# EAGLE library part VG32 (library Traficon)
PCB EUROCARD, 32-pin type C/AC, 5.08 mm
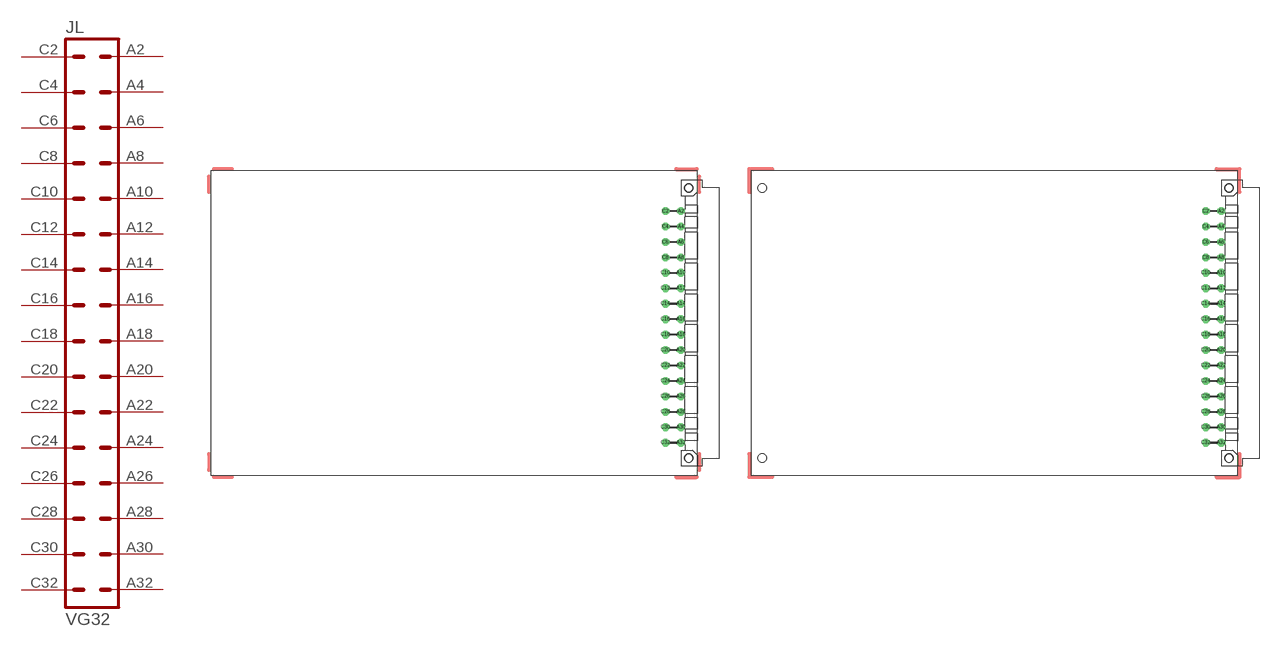
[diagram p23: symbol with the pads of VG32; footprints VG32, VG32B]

Designator prefix JL

## VG32  [VG32]
A2  A2  pas
A4  A4  pas
A6  A6  pas
A8  A8  pas
A10  A10  pas
A12  A12  pas
A14  A14  pas
A16  A16  pas
A18  A18  pas
A20  A20  pas
A22  A22  pas
A24  A24  pas
A26  A26  pas
A28  A28  pas
A30  A30  pas
A32  A32  pas
C2  C2  pas
C4  C4  pas
C6  C6  pas
C8  C8  pas
C10  C10  pas
C12  C12  pas
C14  C14  pas
C16  C16  pas
C18  C18  pas
C20  C20  pas
C22  C22  pas
C24  C24  pas
C26  C26  pas
C28  C28  pas
C30  C30  pas
C32  C32  pas

## VG32B  [VG32B]
Pads as for VG32

## VG32K  [VG32K]
Pads as for VG32

## VG32KB  [VG32KB]
Pads as for VG32

## VG32P  [VG32P]
Pads as for VG32

## Footprint VG32 (pad centres in mm)
EUROCARD, C/AC, 5.08
drill 1.016 pad 2.54 octagon: A2 154.94,36.83; A4 154.94,31.75; A6 154.94,26.67; A8 154.94,21.59; A10 154.94,16.51; A12 154.94,11.43; A14 154.94,6.35; A16 154.94,1.27; A18 154.94,-3.81; A20 154.94,-8.89; A22 154.94,-13.97; A24 154.94,-19.05; A26 154.94,-24.13; A28 154.94,-29.21; A30 154.94,-34.29; A32 154.94,-39.37; C2 149.86,36.83; C4 149.86,31.75; C6 149.86,26.67; C8 149.86,21.59; C10 149.86,16.51; C12 149.86,11.43; C14 149.86,6.35; C16 149.86,1.27; C18 149.86,-3.81; C20 149.86,-8.89; C22 149.86,-13.97; C24 149.86,-19.05; C26 149.86,-24.13; C28 149.86,-29.21; C30 149.86,-34.29; C32 149.86,-39.37
hole 2.794 at 157.48,44.45
hole 2.794 at 157.48,-44.45

## Footprint VG32B (pad centres in mm)
EUROCARD, 4 mounting holes, C/AC, 5.08
drill 1.016 pad 2.54 octagon: A2 154.94,36.83; A4 154.94,31.75; A6 154.94,26.67; A8 154.94,21.59; A10 154.94,16.51; A12 154.94,11.43; A14 154.94,6.35; A16 154.94,1.27; A18 154.94,-3.81; A20 154.94,-8.89; A22 154.94,-13.97; A24 154.94,-19.05; A26 154.94,-24.13; A28 154.94,-29.21; A30 154.94,-34.29; A32 154.94,-39.37; C2 149.86,36.83; C4 149.86,31.75; C6 149.86,26.67; C8 149.86,21.59; C10 149.86,16.51; C12 149.86,11.43; C14 149.86,6.35; C16 149.86,1.27; C18 149.86,-3.81; C20 149.86,-8.89; C22 149.86,-13.97; C24 149.86,-19.05; C26 149.86,-24.13; C28 149.86,-29.21; C30 149.86,-34.29; C32 149.86,-39.37
hole 2.794 at 157.48,44.45
hole 2.794 at 157.48,-44.45
hole 2.794 at 3.81,-44.45
hole 2.794 at 3.81,44.45

## Footprint VG32K (pad centres in mm)
EUROCARD, 2 mounting holes, C/AC, 5.08
drill 1.016 pad 2.54 octagon: A2 154.94,36.83; A4 154.94,31.75; A6 154.94,26.67; A8 154.94,21.59; A10 154.94,16.51; A12 154.94,11.43; A14 154.94,6.35; A16 154.94,1.27; A18 154.94,-3.81; A20 154.94,-8.89; A22 154.94,-13.97; A24 154.94,-19.05; A26 154.94,-24.13; A28 154.94,-29.21; A30 154.94,-34.29; A32 154.94,-39.37; C2 149.86,36.83; C4 149.86,31.75; C6 149.86,26.67; C8 149.86,21.59; C10 149.86,16.51; C12 149.86,11.43; C14 149.86,6.35; C16 149.86,1.27; C18 149.86,-3.81; C20 149.86,-8.89; C22 149.86,-13.97; C24 149.86,-19.05; C26 149.86,-24.13; C28 149.86,-29.21; C30 149.86,-34.29; C32 149.86,-39.37
hole 2.794 at 157.48,44.45
hole 2.794 at 157.48,-44.45

## Footprint VG32KB (pad centres in mm)
EUROCARD, 4 mounting holes, C/AC, 5.08
drill 1.016 pad 2.54 octagon: A2 154.94,36.83; A4 154.94,31.75; A6 154.94,26.67; A8 154.94,21.59; A10 154.94,16.51; A12 154.94,11.43; A14 154.94,6.35; A16 154.94,1.27; A18 154.94,-3.81; A20 154.94,-8.89; A22 154.94,-13.97; A24 154.94,-19.05; A26 154.94,-24.13; A28 154.94,-29.21; A30 154.94,-34.29; A32 154.94,-39.37; C2 149.86,36.83; C4 149.86,31.75; C6 149.86,26.67; C8 149.86,21.59; C10 149.86,16.51; C12 149.86,11.43; C14 149.86,6.35; C16 149.86,1.27; C18 149.86,-3.81; C20 149.86,-8.89; C22 149.86,-13.97; C24 149.86,-19.05; C26 149.86,-24.13; C28 149.86,-29.21; C30 149.86,-34.29; C32 149.86,-39.37
hole 2.794 at 157.48,44.45
hole 2.794 at 157.48,-44.45
hole 2.794 at 3.81,-44.45
hole 2.794 at 3.81,44.45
